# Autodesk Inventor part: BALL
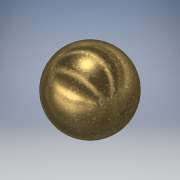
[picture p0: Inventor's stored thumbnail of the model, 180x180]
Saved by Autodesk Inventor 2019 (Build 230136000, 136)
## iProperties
Created: 2021-07
Part Number: BALL
Material: Generic
Document SubType Name: Modeling
Designer: Avinash
Density: 1 g/cm^3
Appearance: Foil Gold
Author: Avinash
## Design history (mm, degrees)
sketch "Sketch1"
  geometry: L1 (0, 15)-(0, -15); A1 r 15 centre (0, 0) between (0, -15) and (0, 15); 1 further point
  constraints: 2 end point, 2 point on circle, 1 centre point, 1 coincident, 1 vertical
  dimensions: "d1" = 15 radius of A1
revolve "Revolution1" sketch "Sketch1" stored, may be unused: angle "d0" = 90 deg
body "Solid1"
